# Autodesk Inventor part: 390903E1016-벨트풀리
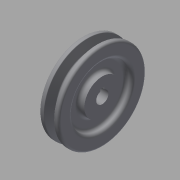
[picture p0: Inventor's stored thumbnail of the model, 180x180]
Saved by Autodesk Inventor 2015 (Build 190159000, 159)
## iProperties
Created: 2019-09
Part Number: 390903E1016-벨트풀리
Material: 일반
Document SubType Name: Modeling
Designer: CAD02
Density: 1 g/cm^3
Appearance: 기본값
Mass: 75.5644 g
Surface Area: 223.132 cm^2
Volume: 75.5644 cm^3
Author: CAD02
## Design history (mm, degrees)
sketch "스케치1"
  geometry: C1 r 42.5 at (0, 0); 1 further point
  constraints: 1 centre point, 1 coincident
  dimensions: "d0" = 85 diameter of C1
extrude "돌출1" new body sketch "스케치1" stored distance "d1" = 19; taper "d2" = 0 deg
sketch "스케치2"
  geometry: L1 (9.5, 42.5)-(9.5, -42.5) reference; L2 (9.5, -42.5)-(-9.5, -42.5) reference; L3 (-9.5, -42.5)-(-9.5, 42.5) reference; L4 (-9.5, 42.5)-(9.5, 42.5) reference; L5 (9.5, 42.5)-(-9.5, 42.5) reference; L6 (4.877, 42.5)-(1.953, 33.5); L7 (1.953, 33.5)-(-1.953, 33.5); L8 (-1.953, 33.5)-(-4.877, 42.5); L9 (4, 39.8)-(-4, 39.8); L10 (0, 42.5)-(0, 33.5); L11 (13.3, 0)-(-13.3, 0) reference; 1 further point
  constraints: 10 end point, 4 point on line, 2 horizontal, 2 midpoint, 1 vertical, 1 other
  dimensions: "d3" = 6.3 distance between parallel lines of L7 L9; "d4" = 2.7 distance between parallel lines of L4 L9; "d5" = 36 deg angle of L8 L6; "d6" = 8 distance of L9.start L9.end
revolve "회전1" sketch "스케치2" stored, may be unused: angle "d7" = 90 deg
fillet "모깎기1" dims "d8" = 2
fillet "모깎기2" dims "d9" = 0.5
fillet "모깎기3" dims "d10" = 1
sketch "스케치3"
  geometry: C1 r 40.5 at (0, 0) reference; C2 r 17.5 at (0, 0); C3 r 29 at (0, 0)
  constraints: 2 centre point, 2 coincident
  dimensions: "d11" = 58 diameter of C3; "d12" = 35 diameter of C2
extrude "돌출2" cut sketch "스케치3" distance "d13" = 6; taper "d14" = 0 deg
fillet "모깎기4" dims "d15" = 3
fillet "모깎기5" dims "d16" = 3
sketch "스케치4"
  geometry: C1 r 17.5 at (0, 0) reference
extrude "돌출3" join sketch "스케치4" distance "d17" = 5; taper "d18" = 0 deg
sketch "스케치5"
  geometry: C1 r 17.5 at (0, 0) reference
hole "구멍1" sketch "스케치5" at (0, 0) diameter "d19" = 12; stored, may be unused: countersink angle "d23" = 90 deg, drill point angle "d25" = 118 deg; dims "d20" = 6, "d21" = 4, "d22" = 2, "d24" = 8
sketch "스케치6"
  geometry: L1 (7.8, 2)-(0, 2); L2 (0, 2)-(0, -2); L3 (0, -2)-(7.8, -2); L4 (7.8, -2)-(7.8, 2); C1 r 6 at (0, 0) reference; 1 further point
  constraints: 8 end point, 2 parallel, 1 coincident, 1 horizontal, 1 midpoint, 1 perpendicular
  dimensions: "d26" = 4 distance of L3.end L1.start; "d27" = 13.8 dimension on C1 L4
extrude "돌출4" cut sketch "스케치6" stored distance "d28" = 5; taper "d29" = 0 deg
node "솔리드1"
mirror "대칭1"
node "절단 모서리 투영1"
